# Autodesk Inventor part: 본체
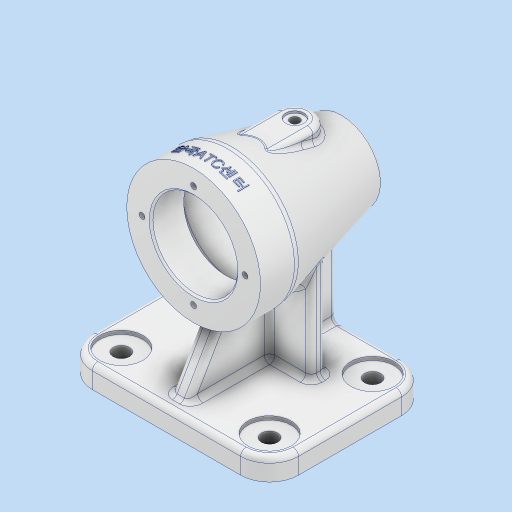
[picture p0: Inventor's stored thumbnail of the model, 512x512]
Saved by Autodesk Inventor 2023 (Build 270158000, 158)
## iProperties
Created: 2024-12
Part Number: 본체
Material: 알루미늄 6061
Document SubType Name: Modeling
Designer: asung
Density: 2.7 g/cm^3
Appearance: 알루미늄 - 평지
Mass: 739.799 g
Surface Area: 674.435 cm^2
Volume: 274 cm^3
Author: asung
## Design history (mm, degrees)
sketch "스케치1"
  geometry: L1 (41, -44.5)-(-41, -44.5); L2 (-57, -28.5)-(-57, 28.5); L3 (-41, 44.5)-(41, 44.5); L4 (57, 28.5)-(57, -28.5); L5 (57, -44.5)-(-57, 44.5); L6 (-57, -44.5)-(57, 44.5); A1 r 16 centre (41, 28.5) between (57, 28.5) and (41, 44.5); A2 r 16 centre (-41, 28.5) between (-41, 44.5) and (-57, 28.5); A3 r 16 centre (-41, -28.5) between (-57, -28.5) and (-41, -44.5); A4 r 16 centre (41, -28.5) between (41, -44.5) and (57, -28.5); 1 further point
  constraints: 12 end point, 8 point on circle, 8 point on line, 8 tangent, 4 centre point, 3 equal radius, 2 midpoint, 2 parallel, 1 horizontal, 1 perpendicular
  dimensions: "d0" = 114 distance of L5.end L6.end; "d1" = 89 distance of L6.start L5.end; "d2" = 16 radius of A1
extrude "돌출1" new body sketch "스케치1" distance "d3" = 12; taper "d4" = 0 deg
node "작업 평면1"
sketch "스케치2"
  geometry: L1 (-16, 0)-(-16, 12) reference; L2 (-16, 12)-(73, 12) reference; L3 (73, 12)-(73, 0) reference; L4 (73, 0)-(-16, 0) reference; L5 (73, 0)-(73, 82); L6 (83, 82)-(-1, 82); L7 (-1, 82)-(-1, 119); L8 (-1, 119)-(19, 119); L9 (19, 119)-(83, 103); L10 (83, 103)-(83, 82); L11 (83, 0)-(83, 82); 1 further point
  constraints: 14 end point, 2 parallel, 2 perpendicular, 1 horizontal, 1 vertical
  dimensions: "d5" = 82 distance of L5.end L3.end; "d6" = 84 distance of L6.start L6.end; "d7" = 20 distance of L7.end L8.end; "d8" = 74 diameter of L8 L6; "d9" = 42 diameter of L9.end L6; "d81" = 10 distance between parallel lines of L5 L11; "d82" = 10 distance between parallel lines of L3 L10; "d83" = 164 diameter of L4 L6; "d84" = 82 distance from line of L11.end L4; "d85" = 0 distance from line of L11.start L4
revolve "회전1" sketch "스케치2" stored, may be unused: angle "d10" = 90 deg
sketch "스케치3"
  geometry: C1 r 37 at (0, 0) reference; 2 further points
  constraints: 1 coincident
hole "구멍1" sketch "스케치3" at (0, 0) diameter "d11" = 47; stored, may be unused: countersink angle "d15" = 90 deg, drill point angle "d17" = 0 deg; dims "d12" = 6, "d13" = 4, "d14" = 2, "d16" = 18
sketch "스케치4"
  geometry: L1 (83, 103)-(83, 61) reference; L2 (83, 61)-(19, 45) reference; L3 (19, 45)-(-1, 45) reference; L4 (-1, 45)-(-1, 58.5) reference; L5 (-1, 58.5)-(17, 58.5) reference; L6 (17, 58.5)-(17, 105.5) reference; L7 (17, 105.5)-(-1, 105.5) reference; L8 (-1, 105.5)-(-1, 119) reference; L9 (-1, 119)-(19, 119) reference; L10 (19, 119)-(83, 103) reference; L11 (-16, 0)-(-16, 12) reference; L12 (-16, 12)-(73, 12) reference; L13 (73, 12)-(73, 0) reference; L14 (73, 0)-(-16, 0) reference; L15 (-1, 58.5)-(-1, 105.5) reference; L16 (83, 103)-(83, 61) reference; L17 (83, 82)-(-1, 82); L18 (105.569, 111)-(97.569, 111); L19 (75, 82)-(75, 97.5); L20 (75, 97.5)-(72, 97.5); L21 (72, 97.5)-(72, 99.5); L22 (72, 99.5)-(62, 99.5); L23 (62, 99.5)-(62, 103.096); L24 (17, 105.5)-(17, 58.5) reference; L25 (62, 103.096)-(17, 114.346); L26 (17, 105.5)-(17, 114.346); 5 further points
  constraints: 18 end point, 4 perpendicular, 3 midpoint, 2 vertical, 1 horizontal, 1 point on line
  dimensions: "d20" = 8 distance of L18.start L18.end; "d21" = 8 distance between parallel lines of L1 L19; "d22" = 31 diameter of L19.end L17; "d23" = 35 diameter of L22 L17; "d24" = 3 distance of L19.end L20.end; "d25" = 10 distance of L21.end L22.end; "d30" = 111 distance between parallel lines of L14 L18; "d31" = 22.5688 distance from line of L18.start L16; "d118" = 5 distance between parallel lines of L10 L25
revolve "회전2" sketch "스케치4" stored, may be unused: angle "d32" = 90 deg
fillet "모깎기1" dims "d33" = 3
fillet "모깎기2" dims "d34" = 0.3
fillet "모깎기4" dims "d36" = 3
chamfer "모따기1" distance "d38" = 1; stored, may be unused: second distance "d39" = 2, angle "d40" = 45 deg
node "작업 평면2"
sketch "스케치5" dims "d42" = 20
  geometry: L1 (16.733, 29.5)-(16.733, 9.5) reference; L2 (-16.733, 9.5)-(-16.733, 29.5) reference; L3 (-16.733, 29.5)-(16.733, 29.5) reference; L4 (-10, -26.5)-(-10, -0.572); L5 (10, -26.5)-(10, -0.572); 4 further points
  constraints: 4 end point, 2 vertical, 1 midpoint, 1 parallel, 1 vertical alignment, 6 other
  dimensions: "d43" = 56 distance from line of L3 point (0, -26.5); "d44" = 20 distance between parallel lines of L4 L5; "d45" = 56 distance from line of L5.start L3
extrude "돌출2" join sketch "스케치5" stored distance "d46" = 10; taper "d47" = 0 deg
fillet "모깎기6" dims "d48" = 3
fillet "모깎기7" dims "d49" = 3
sketch "스케치6"
  geometry: A1 r 7 centre (0, 26.5) between (7, 26.5) and (-7, 26.5) reference; 2 further points
  constraints: 1 coincident
hole "구멍2" sketch "스케치6" at (0, 26.5) diameter "d50" = 10; stored, may be unused: countersink angle "d54" = 90 deg, drill point angle "d56" = 0 deg; dims "d51" = 6, "d52" = 4, "d53" = 2, "d55" = 1
sketch "스케치7"
  geometry: C1 r 5 at (0, 0) reference; 2 further points
  constraints: 1 coincident
hole "구멍3" sketch "스케치7" at (0, 0) diameter "d57" = 5.1881; stored, may be unused: countersink angle "d61" = 90 deg, drill point angle "d63" = 118 deg; dims "d58" = 12, "d59" = 4, "d60" = 2, "d62" = 16
sketch "스케치8" dims "d64" = 57
  geometry: C1 r 23.5 at (0, 0) reference; C2 r 37 at (0, 0) reference; 3 further points
  constraints: 2 vertical alignment, 1 coincident, 2 other
hole "구멍4" sketch "스케치8" at (0, 28.5) diameter "d65" = 3.242; stored, may be unused: countersink angle "d69" = 90 deg, drill point angle "d71" = 118 deg; dims "d66" = 8, "d67" = 4, "d68" = 2, "d70" = 10
sketch "스케치9"
  geometry: L1 (41, 44.5)-(-41, 44.5) reference; L2 (-28, 15.5)-(28, 15.5); L3 (28, 15.5)-(28, 7.5); L4 (28, 7.5)-(-28, 7.5); L5 (-28, 7.5)-(-28, 15.5); L6 (-28, 15.5)-(28, 7.5); L7 (28, 15.5)-(-28, 7.5); 2 further points
  constraints: 12 end point, 2 midpoint, 2 parallel, 1 horizontal, 1 perpendicular, 1 vertical alignment
  dimensions: "d75" = 29 distance from line of L2.start L1; "d76" = 8 distance of L4.end L2.start; "d77" = 56 distance between parallel lines of L3 L5
extrude "돌출3" join sketch "스케치9" stored distance "d78" = 10; taper "d79" = 0 deg
fillet "모깎기9" dims "d87" = 3
fillet "모깎기10" dims "d88" = 10
sketch "스케치10"
  geometry: L1 (9.974, 110.5)-(9, 112.121) reference; L2 (9, 112.121)-(-1, 112.121) reference; L3 (-1, 112.121)-(-1, 119) reference; L4 (-1, 119)-(17.769, 119) reference; L5 (20.194, 118.701)-(34.642, 115.09) reference; L6 (35.369, 115)-(50, 115) reference; L7 (50, 115)-(50, 114) reference; L8 (50, 114)-(52.406, 114) reference; L9 (52.406, 114)-(52.406, 105.495) reference; L10 (17, 105.5)-(-1, 105.5) reference; L11 (-1, 105.5)-(-1, 108.879) reference; L12 (-1, 108.879)-(9, 108.879) reference; L13 (9, 108.879)-(9.974, 110.5) reference; L14 (63, 64.5)-(71.7, 64.5) reference; L15 (72, 64.8)-(72, 66.5) reference; L16 (75, 69.5)-(75, 94.5) reference; L17 (72, 97.5)-(72, 99.2) reference; L18 (71.7, 99.5)-(63, 99.5) reference; L19 (63, 99.5)-(62, 100.5) reference; L20 (62, 100.5)-(62, 100.754) reference; L21 (57.594, 104.198)-(57.594, 114) reference; L22 (57.594, 114)-(60, 114) reference; L23 (60, 114)-(60, 115) reference; L24 (60, 115)-(62, 115) reference; L25 (65, 112)-(65, 109.842) reference; L26 (67.272, 106.932)-(80.728, 103.568) reference; L27 (83, 100.658)-(83, 63.342) reference; L28 (80.728, 60.432)-(44, 51.25) reference; L29 (44, 51.25)-(44, 12) reference; L30 (44, 12)-(73, 12) reference; L31 (73, 12)-(73, 0) reference; L32 (73, 0)-(-16, 0) reference; L33 (-16, 0)-(-16, 12) reference; L34 (-16, 12)-(36, 12) reference; L35 (36, 12)-(36, 49.25) reference; L36 (36, 49.25)-(20.194, 45.299) reference; L37 (17.769, 45)-(-1, 45) reference; L38 (-1, 45)-(-1, 51.879) reference; L39 (-1, 51.879)-(9, 51.879) reference; L40 (9, 51.879)-(9.974, 53.5) reference; L41 (9.974, 53.5)-(9, 55.121) reference; L42 (9, 55.121)-(-1, 55.121) reference; L43 (-1, 55.121)-(-1, 58.5) reference; L44 (-1, 58.5)-(17, 58.5) reference; L45 (62, 63.246)-(62, 63.5) reference; L46 (62, 63.5)-(63, 64.5) reference; L47 (73, 12)-(73, 58.5); L48 (-9, 12)-(10.053, 45); L49 (52.406, 105.495)-(17, 114.346) reference; L50 (17, 114.346)-(17, 105.5) reference; L51 (59.728, 103.664)-(57.594, 104.198) reference; L52 (17, 58.5)-(17, 49.654) reference; L53 (17, 49.654)-(59.728, 60.336) reference; A1 r 10 centre (17.769, 109) between (20.194, 118.701) and (17.769, 119) reference; A2 r 0.3 centre (71.7, 64.8) between (71.7, 64.5) and (72, 64.8) reference; A3 r 3 centre (72, 69.5) between (72, 66.5) and (75, 69.5) reference; A4 r 3 centre (72, 94.5) between (75, 94.5) and (72, 97.5) reference; A5 r 0.3 centre (71.7, 99.2) between (72, 99.2) and (71.7, 99.5) reference; A6 r 3 centre (59, 100.754) between (62, 100.754) and (59.728, 103.664) reference; A7 r 3 centre (62, 112) between (65, 112) and (62, 115) reference; A8 r 3 centre (80, 100.658) between (83, 100.658) and (80.728, 103.568) reference; A9 r 3 centre (80, 63.342) between (80.728, 60.432) and (83, 63.342) reference; A10 r 10 centre (17.769, 55) between (17.769, 45) and (20.194, 45.299) reference; A11 r 3 centre (59, 63.246) between (59.728, 60.336) and (62, 63.246) reference; 1 further point
  constraints: 4 end point, 3 point on line, 1 vertical, 2 other
  dimensions: "d89" = 7 distance from line of L33 L48.start; "d90" = 60 deg angle of L34 L48
  node "절단 모서리 투영4"
feature "리브1" dims "d91" = 1, "d92" = 10, "d93" = 0, "d94" = 0, "d95" = 1, "d96" = 1
feature "리브2" dims "d97" = 1, "d98" = 10, "d99" = 0, "d100" = 0, "d101" = 1, "d102" = 1
fillet "모깎기11" dims "d103" = 3
fillet "모깎기13" dims "d105" = 3
fillet "모깎기14" dims "d106" = 3
fillet "모깎기15" dims "d107" = 3
sketch "스케치11"
  geometry: A1 r 13 centre (41, -28.5) between (41, -41.5) and (54, -28.5) reference; A2 r 13 centre (-41, -28.5) between (-54, -28.5) and (-41, -41.5) reference; A3 r 13 centre (41, 28.5) between (54, 28.5) and (41, 41.5) reference; A4 r 13 centre (-41, 28.5) between (-41, 41.5) and (-54, 28.5) reference; 5 further points
  constraints: 4 coincident
hole "구멍5" sketch "스케치11" at (41, -28.5), (-41, -28.5), (41, 28.5), (-41, 28.5) diameter "d108" = 9; stored, may be unused: countersink angle "d112" = 90 deg, drill point angle "d114" = 0 deg; dims "d109" = 8, "d110" = 24, "d111" = 2, "d113" = 12
node "작업 평면3"
sketch "스케치12"
  geometry: L1 (0, 8.769)-(0, -10) reference; L2 (-37, -10)-(37, -10) reference; 2 further points
  constraints: 1 vertical alignment, 1 other
  dimensions: "d115" = 9 distance from line of L2 point (0, -1)
feature "엠보싱1" sketch "스케치12" dims "d116" = 0.5, "d117" = 0
fillet "모깎기16" dims "d119" = 5
chamfer "모따기2" distance "d120" = 1; stored, may be unused: second distance "d121" = 2, angle "d122" = 45 deg
feature "ҏ耀ґ耀ғ耀ҕ耀җ耀ҙ耀қ耀ҝ耀" dims "d0" = 114, "d1" = 89, "d2" = 16, "d3" = 12, "d4" = 0, "d5" = 82, "d6" = 84, "d7" = 20, "d8" = 74, "d9" = 42, "d10" = 90 deg, "d11" = 47, "d12" = 6, "d13" = 4, "d14" = 2, "d15" = 90 deg, "d16" = 18, "d17" = 0, "d20" = 8, "d21" = 8, "d22" = 31, "d23" = 35, "d24" = 3, "d25" = 10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
node "솔리드1"
pattern_circular "원형 패턴1" dims angle "d73" = 360 deg
node "절단 모서리 투영1"
node "절단 모서리 투영2"
node "절단 모서리 투영3"
node "절단 모서리 투영5"
feature "A9D066F2-1C7D-4E18-AEED-F7BC21143FA4" dims "d11" = 47, "d12" = 6, "d13" = 4, "d14" = 2, "d15" = 90 deg, "d16" = 18, "d17" = 0
